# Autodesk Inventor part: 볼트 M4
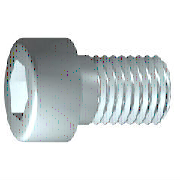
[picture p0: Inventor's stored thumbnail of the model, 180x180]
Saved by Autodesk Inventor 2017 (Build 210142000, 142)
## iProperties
IsCustomPart: 0
Created: 2012-02
Part Number: 볼트 M4
Material: 스테인리스강
Description: 6각 소켓 머리 캡 나사
Document SubType Name: Modeling
Standard: ISO 4762
Designer: mduedu
Standard Revision: Fourth edition 2004-03-01
Standards Organization: ISO
Language: ko-KR
Size Designation: M4 x 10
Categories: <MemberInstance><Categories><Category DisplayName="조임쇠" InternalName="e4da775c-781d-43d5-af7c-5136215cf5a6" Mnemonic="FSTN"><Category DisplayName="볼트" InternalN
Density: 8.08 g/cm^3
Appearance: 반광택
Author: mduedu
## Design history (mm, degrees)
sketch "스케치1"
  geometry: L1 (-1, 0)-(10, 0); L2 (10, 0)-(10, 2); L3 (10, 2)-(1.75, 2); L4 (1.75, 2)-(1.32, 2); L5 (1.32, 2)-(0, 2); L6 (0, 2)-(0, 3.5); L7 (0, 3.5)-(-4, 3.5); L8 (-4, 3.5)-(-4, 1.732); L9 (-4, 1.732)-(-2, 1.732); L10 (-2, 1.732)-(-1, 0); L11 (-6.8, 0)-(12.8, 0) reference; L12 (0, -0.7)-(0, 4.2) reference; L13 (1.75, 2)-(0, 2)
  constraints: 22 end point, 6 parallel, 2 collinear, 2 perpendicular, 1 horizontal, 1 point on line
  dimensions: "d1" = 8.25 distance from line of L3.end L2 (= GEL); "d2" = 0.42952 distance of L4.end L3.end (computed from GAL); "d3" = 4 distance between parallel lines of L8 L6 (= KOH); "d4" = 2 distance of L8.end L9.end (= INTI); "d5" = 60 deg angle of L10 L1; "d6" = 4 diameter of L3 L1 (= GD); "d7" = 4 diameter of L5 L1 (= BDM); "d8" = 3.4641 diameter of L9 L1 (= 1.1547 x SW); "d9" = 7 diameter of L7 L1 (= KOD); "d26" = 10 distance between parallel lines of L12 L2 (= NLG)
revolve "본체" sketch "스케치1" stored, may be unused: angle "d10" = 90 deg
sketch "스케치2"
  geometry: L1 (0, -4.9)-(0, 4.9) reference; L2 (-4.9, 0)-(4.9, 0) reference; L3 (1.732, 0)-(0.866, -1.5); L4 (0.866, -1.5)-(-0.866, -1.5); L5 (-0.866, -1.5)-(-1.732, 0); L6 (-1.732, 0)-(-0.866, 1.5); L7 (-0.866, 1.5)-(0.866, 1.5); L8 (0.866, 1.5)-(1.732, 0); 2 further points
  constraints: 12 end point, 1 coincident, 1 horizontal alignment, 1 point on line, 12 other
extrude "슬롯" join sketch "스케치2" stored distance "d11" = 10; taper "d12" = 0 deg
workplane "Work Plane1"
fillet "Fillet2" dims "d30" = 0.1 (= R)
body "Solid1"
fillet "모깎기1" dims "d17" = 0.4 (= RR)
feature "스레드" dims "d13" = 8.25 (= GEL), "d14" = 0
chamfer "모따기1" distance "d15" = 0.42941 (= -0.5 x SPD + 0.5 x GD); stored, may be unused: second distance "d16" = 0.42941 (= GUL), angle "d27" = 45 deg
other parameters: "GD" = 4 [user parameter; used in 2 equation terms], "NLG" = 10 [user parameter; used in 1 equation term], "GEL" = 8.25 [user parameter; used in 2 equation terms], "KOD" = 7 [user parameter; used in 1 equation term], "KOH" = 4 [user parameter; used in 1 equation term], "INTI" = 2 [user parameter; used in 1 equation term], "GAL" = 0.42941 (= 0.61345 x PTC) [user parameter; used in 1 equation term], "GUL" = 0.42941 (= 0.61345 x PTC) [user parameter; used in 1 equation term], "BDM" = 4 (= NND) [user parameter; used in 1 equation term], "SW" = 3 [user parameter; used in 2 equation terms], "RR" = 0.4 [user parameter; used in 1 equation term], "SPD" = 3.14117 (= NND - 1.2269 x PTC) [user parameter; used in 1 equation term], "d19" = 0, "d28" = 0, "d29" = 0, "R" = 0.1 [user parameter; used in 1 equation term], "TOA" = 30 deg [user parameter], "GD1" = 3.14117 (= THREADDIA - 1.2269 x PTC) [user parameter], "THREADDIA" = 4 [user parameter; used in 1 equation term], "FAWI" = 45 deg [user parameter], "TPU" = 14.28571 (computed from PTC) [user parameter], "PTC" = 0.7 [user parameter; used in 5 equation terms], "NND" = 4 [user parameter; used in 2 equation terms], "E0" = 3.465 (= 1.155 x SW) [user parameter]
